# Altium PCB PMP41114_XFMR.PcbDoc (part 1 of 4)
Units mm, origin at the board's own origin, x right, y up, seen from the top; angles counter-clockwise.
Board outline 70 x 173.04 mm, 10 copper layers (Top Layer, Layer 2, Layer 3, Layer 4, Layer 5, Layer 6, Layer 7, Layer 8, Layer 9, Bottom Layer 1), stack 2.98 mm thick; 147 components, 149 nets, 547 pads, 972 vias.
Unrouted connection lines stored in the file: 2.
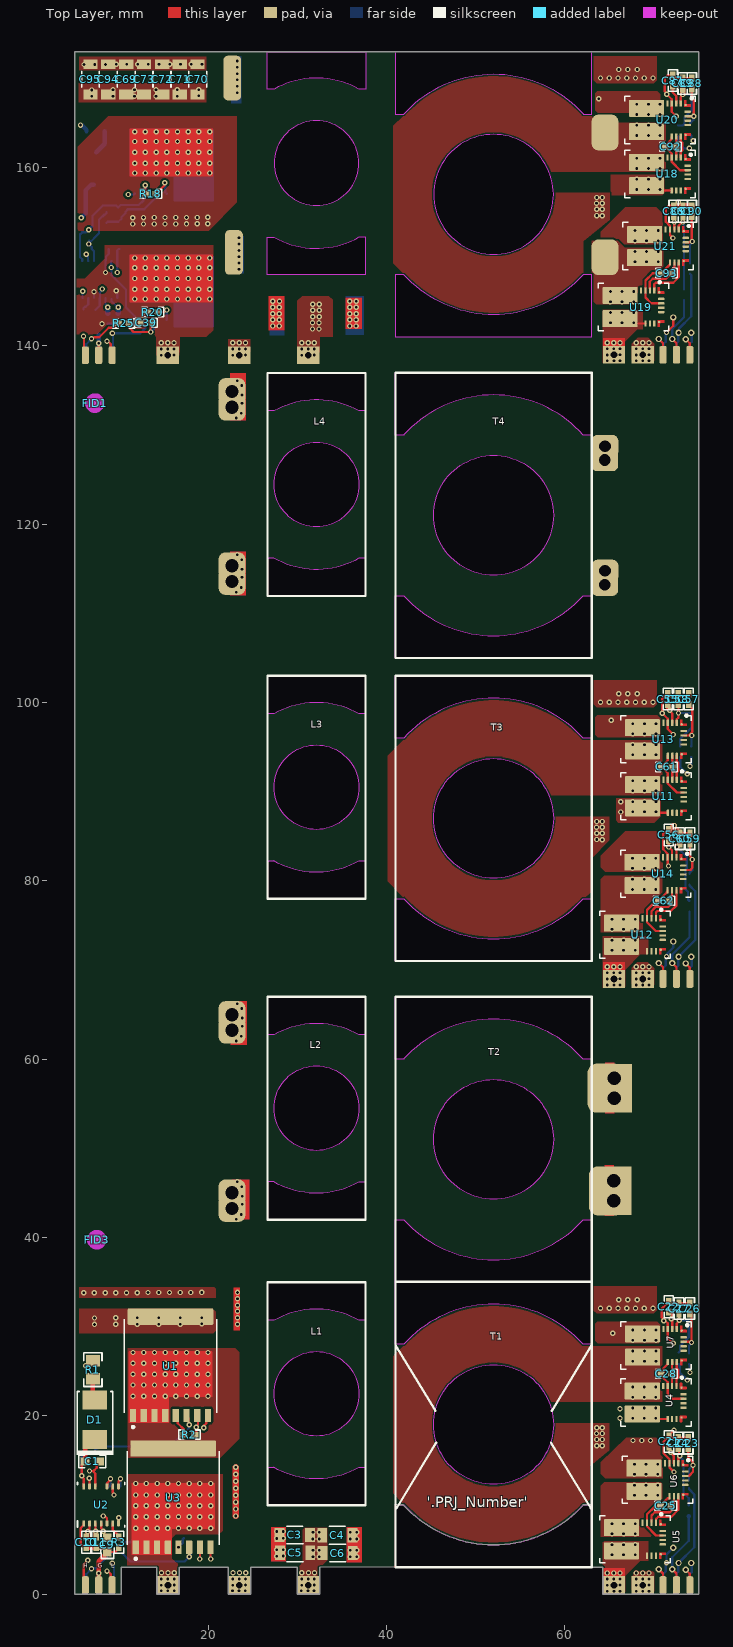
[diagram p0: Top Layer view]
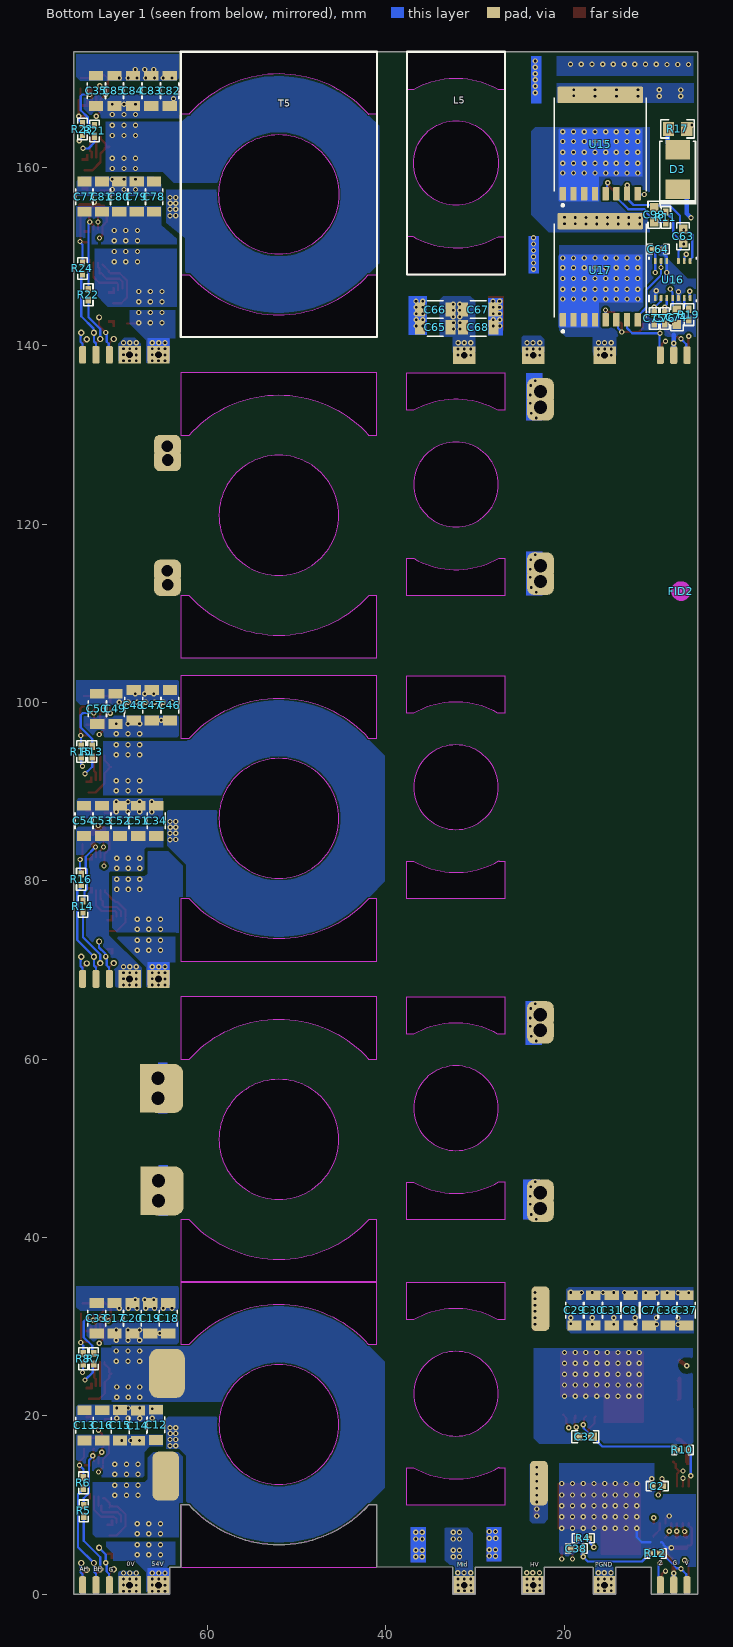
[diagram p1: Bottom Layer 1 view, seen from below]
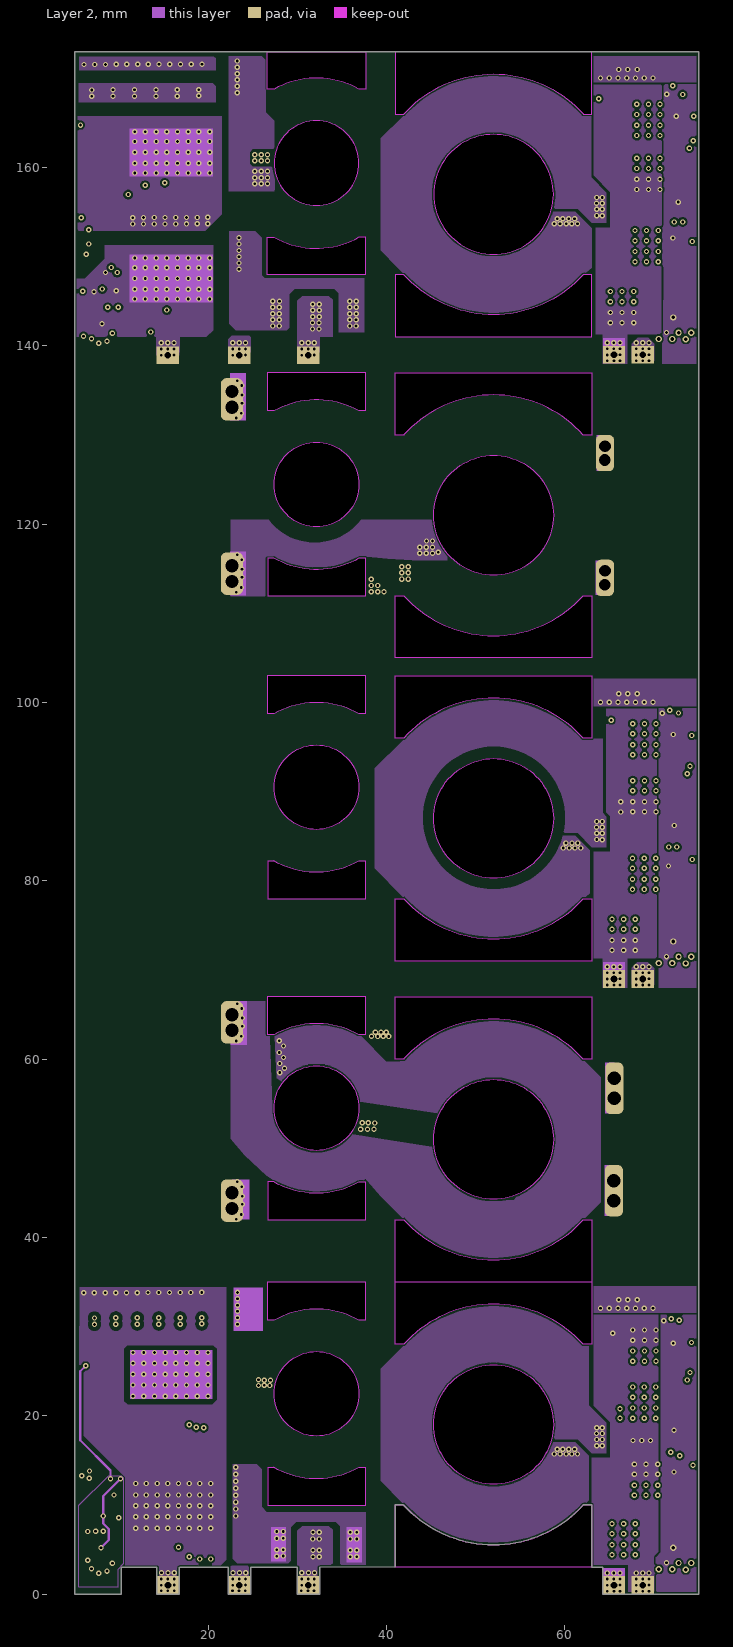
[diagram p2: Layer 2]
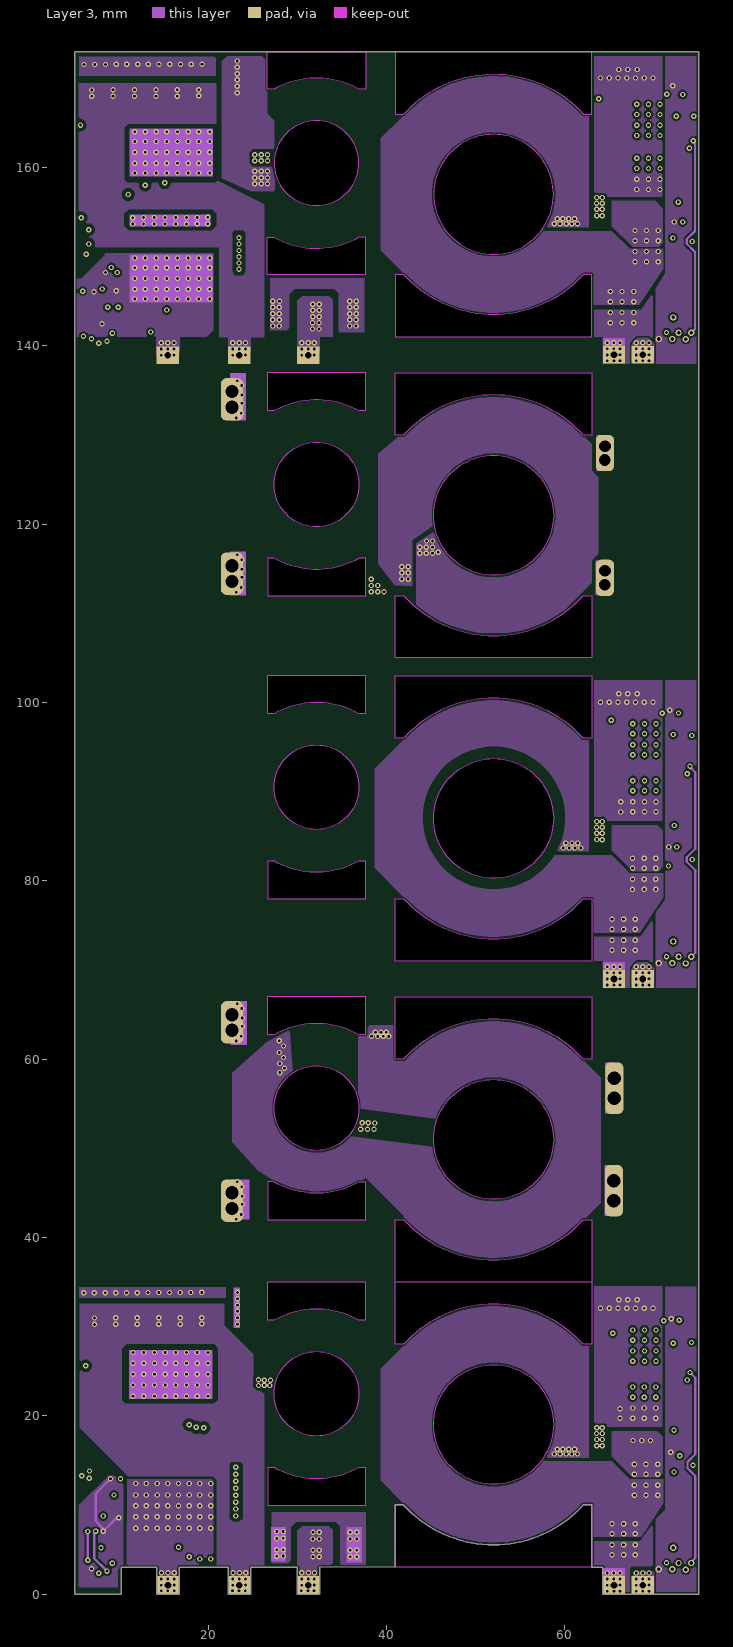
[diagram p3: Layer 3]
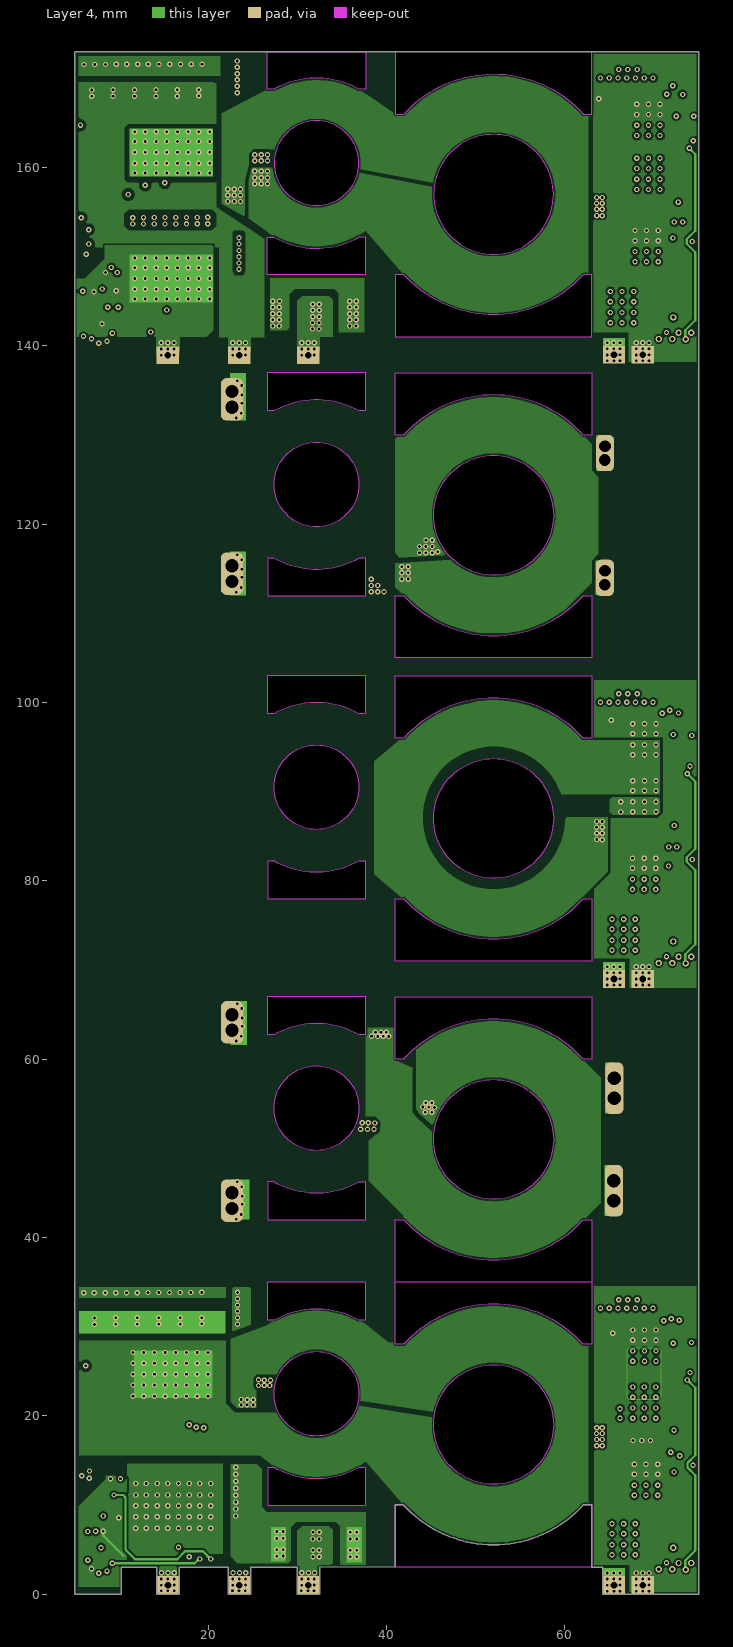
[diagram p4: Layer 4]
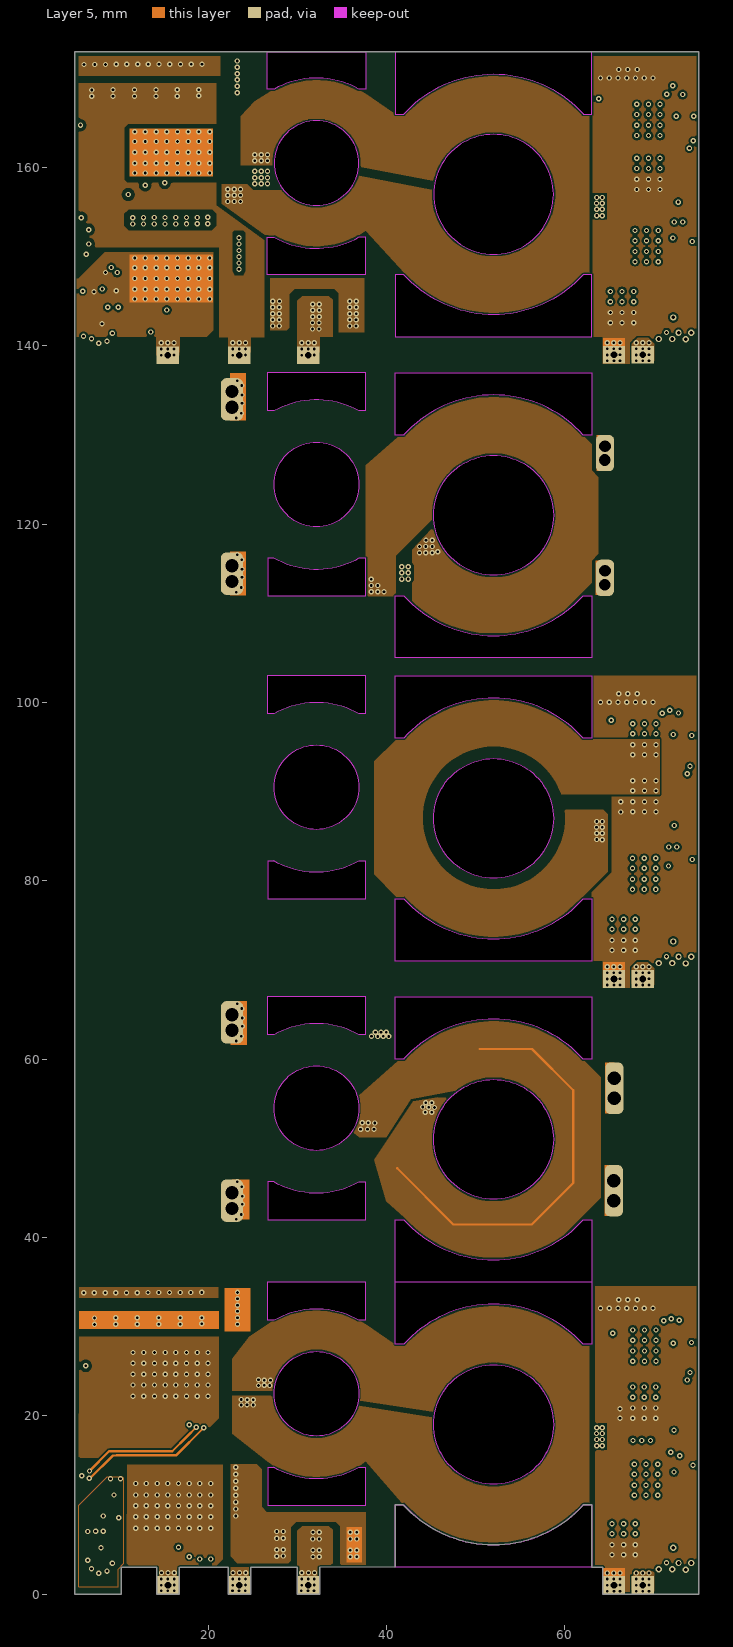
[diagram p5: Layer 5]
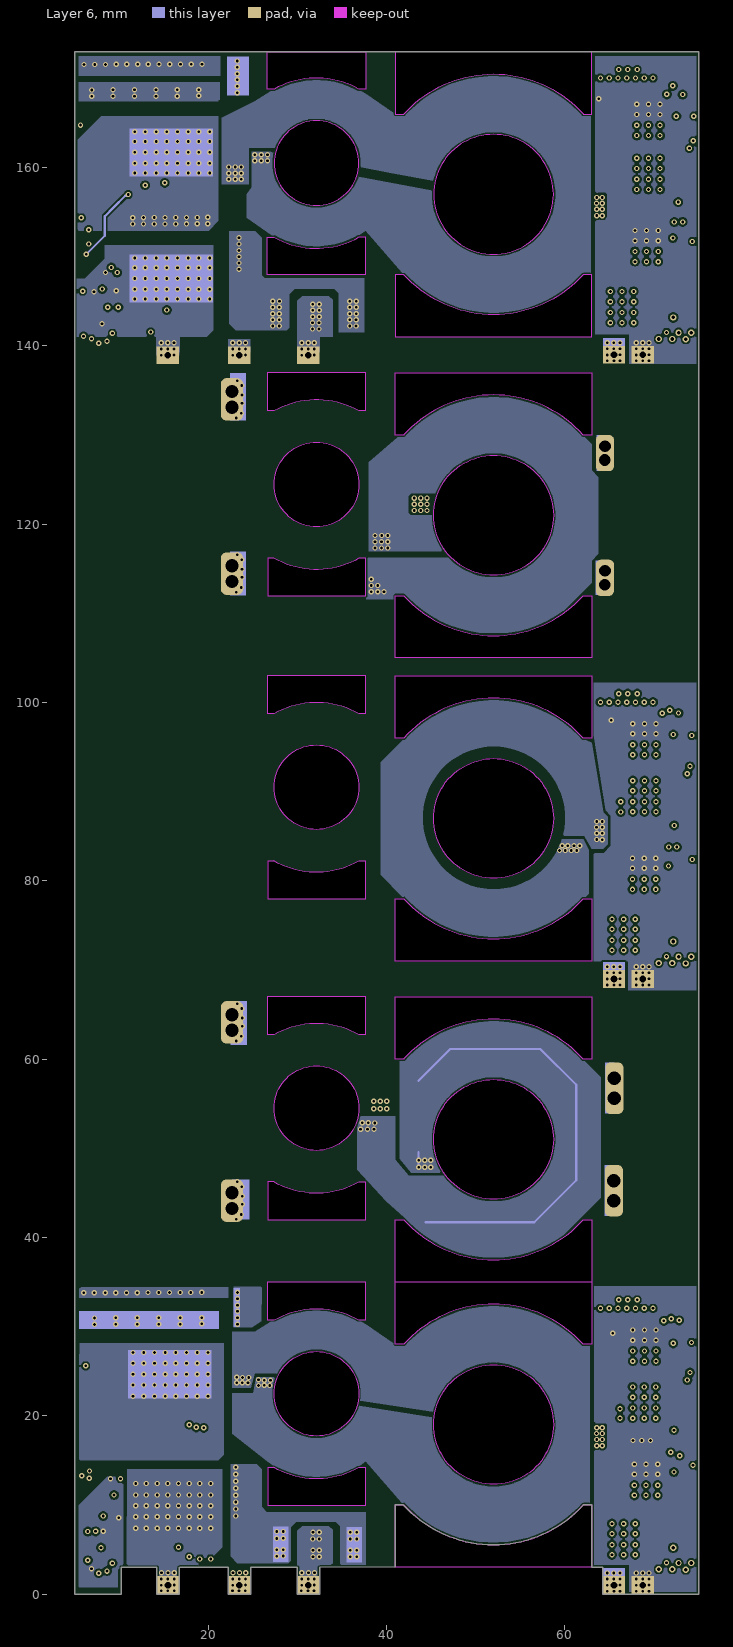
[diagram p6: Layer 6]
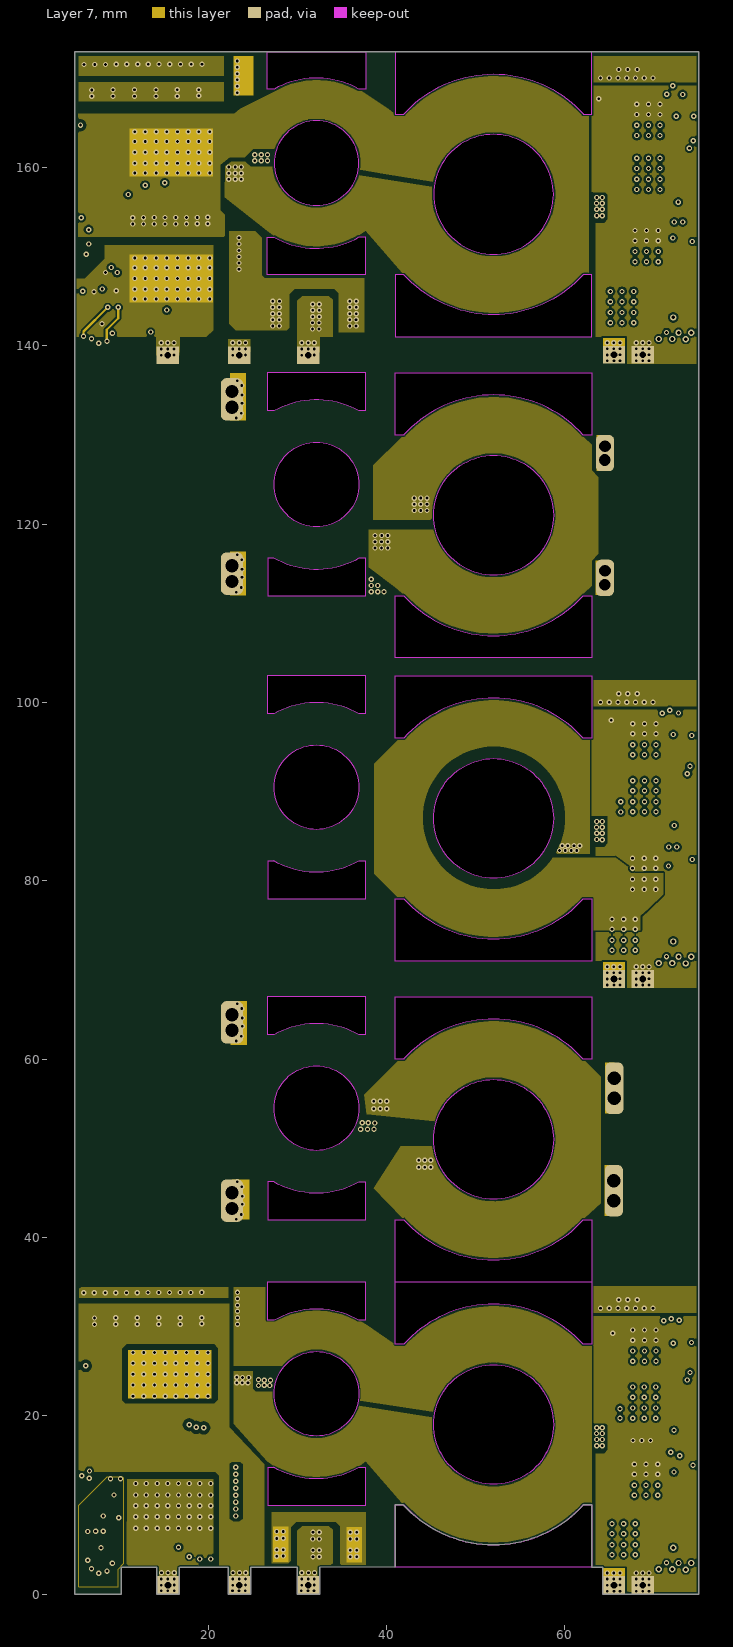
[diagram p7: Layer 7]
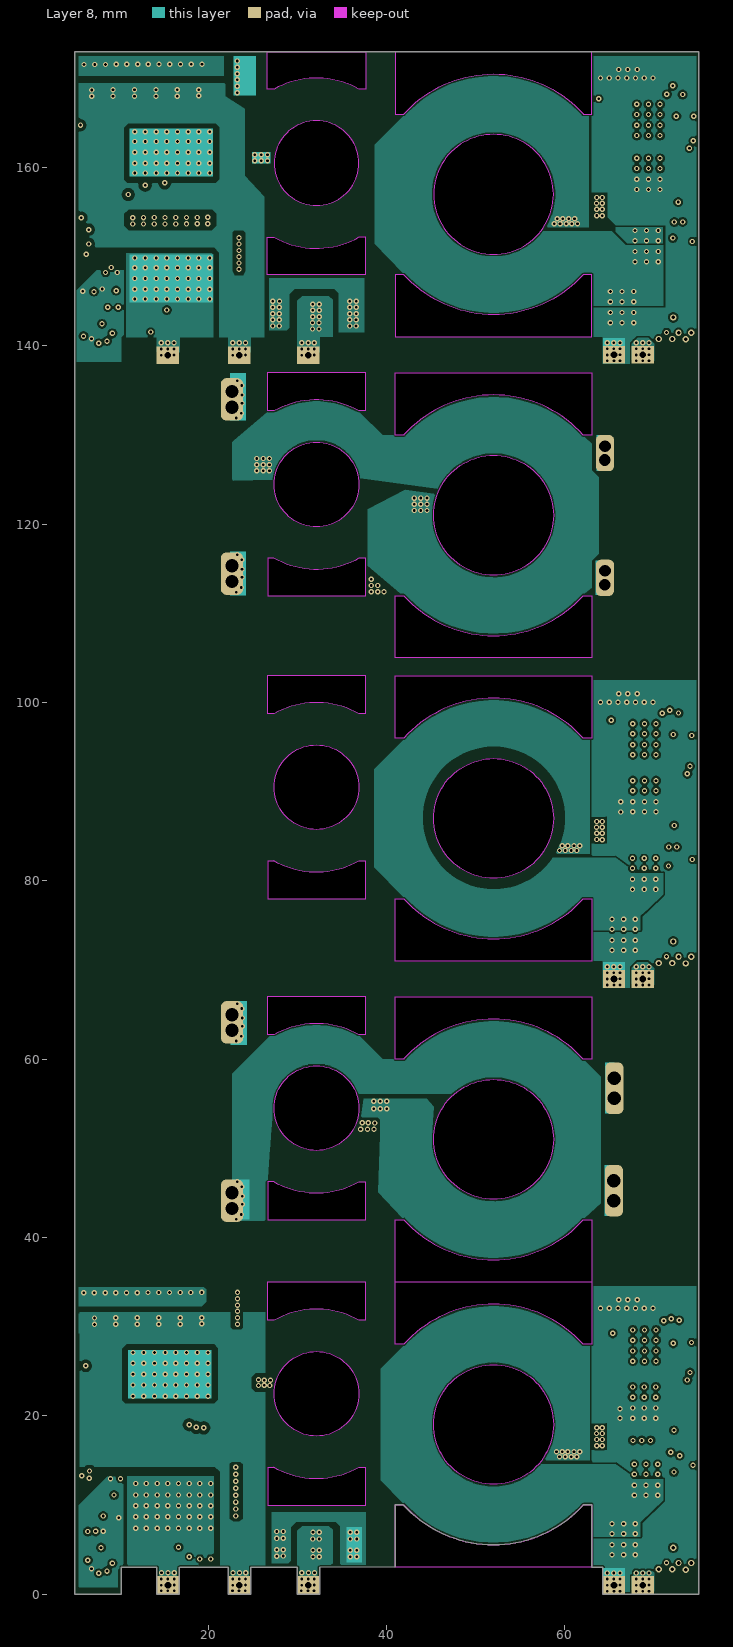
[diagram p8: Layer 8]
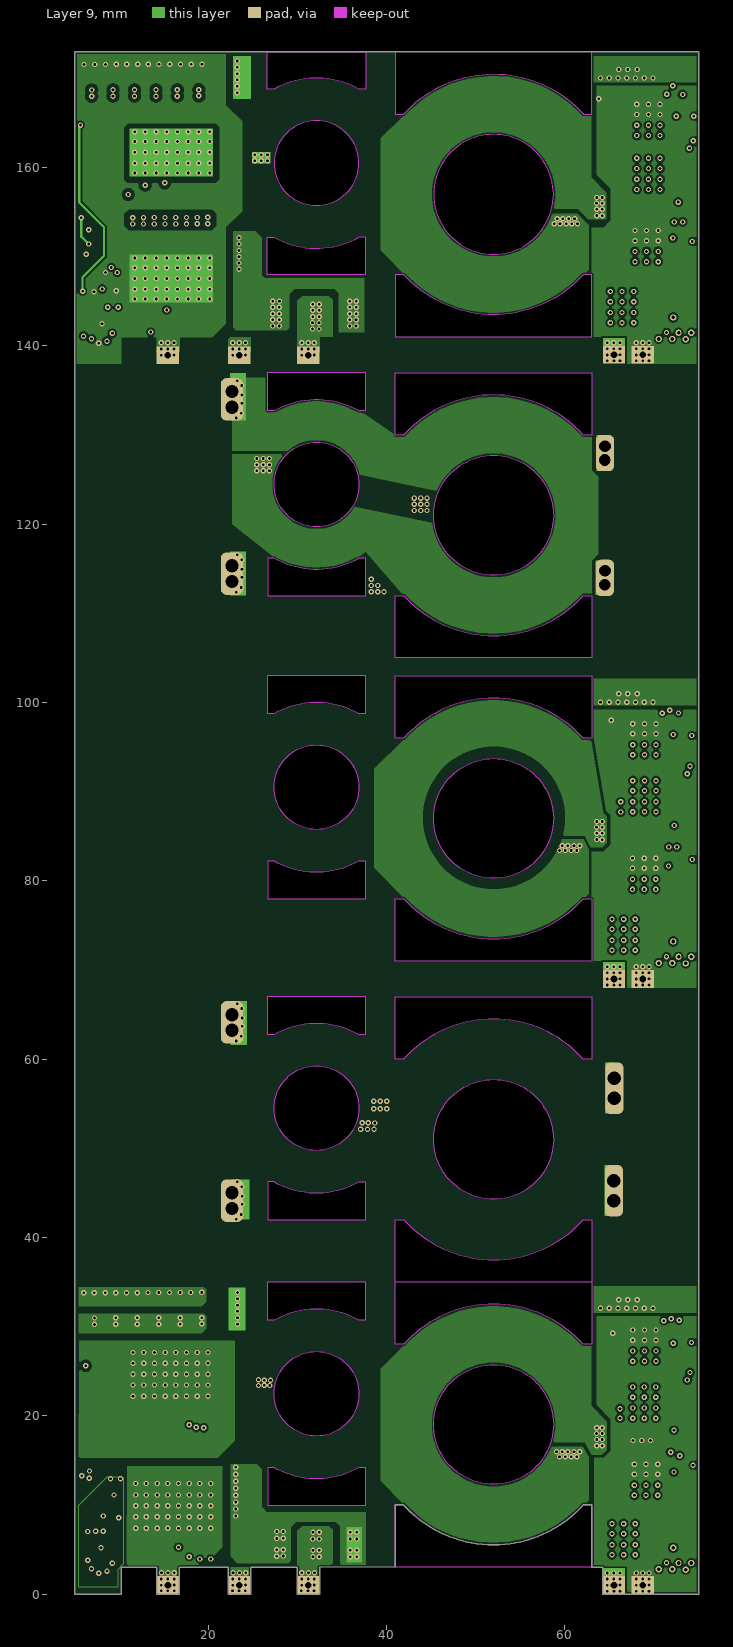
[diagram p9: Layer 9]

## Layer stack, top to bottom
Top Solder: solder mask 0.0102, Solder Resist, Dk 3.5
Top Layer: signal copper 0.07
Dielectric 7: prepreg 0.2, PP-006, Dk 4.1
Layer 2: signal copper 0.105
Dielectric 1: core 0.25, PP-006, Dk 4.1
Layer 3: signal copper 0.105
Dielectric 2: prepreg 0.2, PP-006, Dk 4.1
Layer 4: signal copper 0.105
Dielectric 3: core 0.25, PP-006, Dk 4.1
Layer 5: signal copper 0.105
Dielectric1: prepreg 0.2, FR-4 High Tg, Dk 4.8
Layer 6: signal copper 0.105
Dielectric 4: core 0.25, PP-006, Dk 4.1
Layer 7: signal copper 0.105
Dielectric 5: prepreg 0.2, PP-006, Dk 4.1
Layer 8: signal copper 0.105
Dielectric 6: core 0.25, PP-006, Dk 4.1
Layer 9: signal copper 0.105
Dielectric 8: prepreg 0.2, PP-006, Dk 4.1
Bottom Layer 1: signal copper 0.07
Bottom Solder: solder mask 0.0102, Solder Resist, Dk 3.5

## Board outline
5,0 10.25,0 10.25,3 14.231,3 14.231,-0.038 16.75,-0.038 16.75,2.962 16.78,3 22.243,3 22.243,0 24.784,0 24.784,3 29.993,3 29.993,0 32.5,0 32.5,3 41,3.064 41,10.012 41.883,10 ccw(c51.986,19.186) 62.088,10 63,10 63,3.018 64.25,3.018 64.25,0 75,0 75,173 5,173

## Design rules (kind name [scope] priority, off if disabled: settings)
AcuteAngle [All] p1: minimum=4.50000000000000E+0001 checktracksonly=TRUE
AssemblyTestPointUsage [All] p1: valid=2
BoardOutlineClearance BoardOutlineClearance_MountingHoles [OnCopper and InComponentClass('Mounting Holes')] p1: gap=0.5 ignorepadtopadclearanceinfootprint=FALSE
BoardOutlineClearance BoardOutlineClearance_Poly [OnCopper and IsPoly] p2: gap=0.254 ignorepadtopadclearanceinfootprint=FALSE
BoardOutlineClearance [OnCopper and Not InComponentClass('Logo') and not InComponentClass('FiducialMark') and not InRegion(1000,500,4000,800) and not InPoly] p3: gap=0.254 ignorepadtopadclearanceinfootprint=FALSE
Clearance Clearance_Surface [(IsPolygon AND InLayerClass('Component Layers'))] p1: gap=0.178 ignorepadtopadclearanceinfootprint=FALSE
Clearance Clearance_Keepouts [((IsTrack Or IsArc) And Not InPoly) And IsFree and IsKeepOut vs ((IsTrack Or IsArc) And Not InPoly) And IsFree and IsKeepOut] p2: gap=0 ignorepadtopadclearanceinfootprint=FALSE
Clearance Clearance_Poly [InPolygon] p3: gap=0.229 ignorepadtopadclearanceinfootprint=TRUE
Clearance Clearance_FiducialMark [IsKeepOut and InComponentClass('FiducialMark') vs IsPad and InComponentClass('FiducialMark')] p4: gap=0 ignorepadtopadclearanceinfootprint=FALSE
Clearance Clearance_1 [(ExistsOnLayer('Layer 2') Or ExistsOnLayer('Layer 3') Or ExistsOnLayer('Layer 4') Or ExistsOnLayer('Layer 5') Or ExistsOnLayer('Layer 6') Or ExistsOnLayer('Layer 7') Or ExistsOnLayer('Layer 8') Or ExistsOnLayer('Layer 9')) vs (ExistsOnLayer('Layer 2') Or ExistsOnLayer('Layer 3') Or ExistsOnLayer('Layer 4') Or ExistsOnLayer('Layer 5') Or ExistsOnLayer('Layer 6') Or ExistsOnLayer('Layer 7') Or ExistsOnLayer('Layer 8') Or ExistsOnLayer('Layer 9'))] p5: gap=0.2 ignorepadtopadclearanceinfootprint=TRUE sourcerule=57 cellrowname=All cellrowtype=0 cellcolname=All cellcoltype=0 innerlayers=TRUE
Clearance Clearance_2 [(ExistsOnLayer('Top Layer') Or ExistsOnLayer('Bottom Layer 1')) vs (ExistsOnLayer('Top Layer') Or ExistsOnLayer('Bottom Layer 1'))] p6: gap=0.2 ignorepadtopadclearanceinfootprint=TRUE sourcerule=57 cellrowname=All cellrowtype=0 cellcolname=All cellcoltype=0 outerlayers=TRUE
Clearance [All] p7: gap=0.2 ignorepadtopadclearanceinfootprint=TRUE ismatrix=TRUE
ComponentClearance ComponentClearance_MountingHoles_FiducialMarks [InComponentClass('Mounting Holes') vs InComponentClass('FiducialMark')] p1: gap=1.27 collisioncheckmode=3 verticalgap=0.254 showdistances=FALSE
ComponentClearance ComponentClearance_Shunt [InComponentClass('Header') vs InComponentClass('Shunt')] p2: gap=0 collisioncheckmode=3 verticalgap=0 showdistances=FALSE
ComponentClearance ComponentClearance_Logo [InComponentClass('Logo')] p3: gap=0.762 collisioncheckmode=3 verticalgap=0.254 showdistances=FALSE
ComponentClearance ComponentClearance_ScrewToNut [(HasFootprint('NY PMS 440 0025 PH')) vs (HasFootprint('Keystone_1902C'))] p4: gap=0.127 collisioncheckmode=3 verticalgap=0.254 showdistances=FALSE
ComponentClearance ComponentClearance_MountingHoles [InComponentClass('Mounting Holes')] p5: gap=2.54 collisioncheckmode=3 verticalgap=2540 showdistances=FALSE
ComponentClearance ComponentClearance_SmallPassives [HasFootprint('0201*') or HasFootprint('0402*') or HasFootprint('0508') or HasFootprint('0603*') or HasFootprint('0612') or HasFootprint('0805*') or HasFootprint('0815*') or HasFootprint('0830*') or HasFootprint('1206*') or HasFootprint('1210*') or HasFootprint('1808*') or HasFootprint('1812*') or HasFootprint('1825*') or HasFootprint('2010*') or HasFootprint('2220*') or HasFootprint('2225*') or HasFootprint('2512*') or HasFootprint('2728*') or HasFootprint('3518*') vs HasFootprint('0201*') or HasFootprint('0402*') or HasFootprint('0508') or HasFootprint('0603*') or HasFootprint('0612') or HasFootprint('0805*') or HasFootprint('0815*') or HasFootprint('0830*') or HasFootprint('1206*') or HasFootprint('1210*') or HasFootprint('1808*') or HasFootprint('1812*') or HasFootprint('1825*') or HasFootprint('2010*') or HasFootprint('2220*') or HasFootprint('2225*') or HasFootprint('2512*') or HasFootprint('2728*') or HasFootprint('3518*')] p6 off: gap=0.38 collisioncheckmode=3 verticalgap=0.254 showdistances=FALSE
ComponentClearance ComponentClearance_THtoSMT [IsThruComponent vs IsSMTComponent] p7: gap=0.762 collisioncheckmode=3 verticalgap=0.762 showdistances=FALSE
ComponentClearance ComponentClearance_THtoTH [IsThruComponent vs IsThruComponent] p8: gap=0.508 collisioncheckmode=3 verticalgap=0.762 showdistances=FALSE
ComponentClearance [All] p9: gap=0 collisioncheckmode=3 verticalgap=0.254 showdistances=FALSE
FabricationTestPointUsage TestPointUsage [All] p1: valid=2 allowmultiple=FALSE
FabricationTestpoint Testpoint [All] p1: side=3 testpointundercomponent=TRUE minsize=1.016 maxsize=2.54 preferedsize=1.524 minholesize=0 maxholesize=1.016 preferedholesize=0.813 testpointgrid=0.025 allowsidetop=TRUE allowsidebottom=TRUE usegrid=TRUE gridtolerance=0
FanoutControl Fanout_LCC [IsLCC] p1: bgadir=Out bgaviamode=Centered fanoutstyle=Auto fanoutdirection=Alternating viagrid=0.025 // Fanout_LCC (Default Rule)
FanoutControl Fanout_BGA [IsBGA] p2: bgadir=Out bgaviamode=Centered fanoutstyle=Auto fanoutdirection=Alternating viagrid=0.025 // Fanout_BGA (Default Rule)
FanoutControl Fanout_Default [All] p4: bgadir=Out bgaviamode=Centered fanoutstyle=Auto fanoutdirection=Alternating viagrid=0.025 // Fanout_Default (Default Rule)
FanoutControl Fanout_Small [(CompPinCount < 5)] p5: bgadir=Out bgaviamode=Centered fanoutstyle=Auto fanoutdirection=OutThenIn viagrid=0.025 // Fanout_Small (Default Rule)
HoleSize [All] p1: absolutevalues=TRUE maxlimit=6.375 minlimit=0.2 maxpercent=80.000 minpercent=20.000
MinimumAnnularRing MinimumAnnularRing_ThermalPadVias [IsVia and InAnyComponent] p1: minimumring=0.15
MinimumAnnularRing [All] p2: minimumring=0.15
MinimumSolderMaskSliver MinimumSolderMaskSliver_Logo [InComponentClass('Logo') vs InComponentClass('Logo')] p1: minsoldermaskwidth=0.018
MinimumSolderMaskSliver [All] p2: minsoldermaskwidth=0.1
PlaneConnect [All] p1: planeconnectstyle=Relief reliefexpansion=0.254 reliefentries=4 reliefconductorwidth=0.254 reliefairgap=0.254
PolygonConnect [All] p1: connectstyle=Direct reliefconductorwidth=0.254 reliefentries=4 polygonreliefangle="90 Angle" airgapwidth=0.254
RoutingVias [All] p1: holewidth=0.711 width=1.27 viastyle="Through Hole" minholewidth=0.3 minwidth=0.6 maxholewidth=0.711 maxwidth=1.27
SilkToBoardRegionClearance [Not ((IsComment or IsDesignator) And (Hide <> 'False')) and not InRegion(1000,500,4000,800)] p1:
SilkToSilkClearance SilkToSilkClearance_Pb-FreeLogo [(HasFootprint('Pb-Free_Overlay_Medium') OR HasFootprint('Pb-Free_Overlay_Small')) vs (HasFootprint('Pb-Free_Overlay_Medium') OR HasFootprint('Pb-Free_Overlay_Small'))] p1: silktosilkclearance=0
SilkToSilkClearance [All] p2: silktosilkclearance=0.1
SilkToSolderMaskClearance SilkToComponentPadClearance [(IsPad or IsFill or IsRegion) and InAnycomponent] p1: minsilkscreentomaskgap=0.127 clearancetoexposedcopper=TRUE
SilkToSolderMaskClearance "Silk to Solder Mask Opening" [All] p2: minsilkscreentomaskgap=0.1 clearancetoexposedcopper=FALSE
SolderMaskExpansion [All] p1: expansion=0.05 istentingtop=FALSE
UnRoutedNet [All] p1: checkbadconnections=TRUE
Width [All] p1: maxlimit=2 minlimit=0.254 preferedwidth=0.254
15 further rules are at their usual default settings.

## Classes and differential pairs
component class PMP41114_D2D_Sheet5: C35 C39 C63 C64 C65 C66 C67 C68 C69 C70 C71 C72 C73 C74 C75 C76 C77 C78 C79 C80 C81 C82 C83 C84 C85 C86 C87 C88 C89 C90 C91 C92 C93 C94 C95 C98 D3 R11 R17 R18 R19 R20 R21 R22 R23 R24 R25 U15 U16 U17 U18 U19 U20 U21
component class PMP41114_D2D_Sheet3: C34 C46 C47 C48 C49 C50 C51 C52 C53 C54 C55 C56 C57 C58 C59 C60 C61 C62 R13 R14 R15 R16 U11 U12 U13 U14
component class PMP41114_D2D_Sheet1: C1 C2 C3 C4 C5 C6 C7 C8 C9 C10 C11 C12 C13 C14 C15 C16 C17 C18 C19 C20 C21 C22 C23 C24 C25 C26 C27 C28 C29 C30 C31 C32 C33 C36 C37 C38 D1 L1 R1 R2 R3 R4 R5 R6 R7 R8 R10 R12 T1 U1 U2 U3 U4 U5 U6 U7
component class PMP41114_D2D_Hardware: !PCB FID1 FID2 FID3 L2 L3 L4 L5 T2 T3 T4 T5
component class FiducialMark: FID1 FID2 FID3

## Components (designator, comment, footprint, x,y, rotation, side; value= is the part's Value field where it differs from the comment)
C1 "CGJ3E1X7R1E105K080AC" 0603 6.987,14.87 r0 top value=1uF
C2 "C1005X7R1H104K050BB" 0402 9.561,12.102 r0 bottom value=0.1uF
C3 "C1206C223KDRACTU" 1206_190 29.702,6.627 r0 top value=0.022uF
C4 "C1206C223KDRACTU" 1206_190 34.489,6.598 r180 top value=0.022uF
C5 "C1206C223KDRACTU" 1206_190 29.732,4.622 r0 top value=0.022uF
C6 "C1206C223KDRACTU" 1206_190 34.517,4.599 r180 top value=0.022uF
C7 "C1206C223KDRACTU" 1206_190 10.485,31.82 r90 bottom value=0.022uF
C8 "C1206C223KDRACTU" 1206_190 12.572,31.82 r90 bottom value=0.022uF
C9 "CGJ3E1X7R1E105K080AC" 0603 8.695,5.515 r270 top value=1uF
C10 "885012205055" 0402 6.323,5.805 r270 top value=100pF
C11 "885012205055" 0402 7.421,5.805 r270 top value=100pF
C12 "GRM31CZ72A475KE11L" 1206_180 65.782,18.977 r270 bottom value=4.7uF
C13 "GRM31CZ72A475KE11L" 1206_180 73.798,18.919 r270 bottom value=4.7uF
C14 "GRM31CZ72A475KE11L" 1206_180 67.803,18.905 r270 bottom value=4.7uF
C15 "GRM31CZ72A475KE11L" 1206_180 69.81,18.933 r270 bottom value=4.7uF
C16 "GRM31CZ72A475KE11L" 1206_180 71.802,18.923 r270 bottom value=4.7uF
C17 "GRM31CZ72A475KE11L" 1206_180 70.432,30.942 r270 bottom value=4.7uF
C18 "GRM31CZ72A475KE11L" 1206_180 64.417,30.942 r270 bottom value=4.7uF
C19 "GRM31CZ72A475KE11L" 1206_180 66.438,30.942 r270 bottom value=4.7uF
C20 "GRM31CZ72A475KE11L" 1206_180 68.428,30.942 r270 bottom value=4.7uF
C21 "GRM155R71H104ME14D" 0402 71.684,17.122 r90 top value=0.1uF
C22 "GRM155R71H104ME14D" 0402 71.656,32.224 r90 top value=0.1uF
C23 "CC0402KRX7R9BB101" 0402 73.85,16.934 r90 top value=100pF
C24 "CC0402KRX7R9BB101" 0402 72.725,16.934 r90 top value=100pF
C25 "C1005X7R1H104K050BE" 0402 71.331,9.913 r180 top value=0.1uF
C26 "CC0402KRX7R9BB101" 0402 74.023,32.031 r90 top value=100pF
C27 "CC0402KRX7R9BB101" 0402 72.804,32.031 r90 top value=100pF
C28 "C1005X7R1H104K050BE" 0402 71.389,24.718 r180 top value=0.1uF
C29 "C1206C223KDRACTU" 1206_190 18.834,31.82 r90 bottom value=0.022uF
C30 "C1206C223KDRACTU" 1206_190 16.747,31.82 r90 bottom value=0.022uF
C31 "C1206C223KDRACTU" 1206_190 14.659,31.82 r90 bottom value=0.022uF
C32 "CGJ3E1X7R1E105K080AC" 0603 17.623,17.644 r0 bottom value=1uF
C33 "GRM31CZ72A475KE11L" 1206_180 72.436,30.942 r270 bottom value=4.7uF
C34 "GRM31CZ72A475KE11L" 1206_180 65.761,86.717 r270 bottom value=4.7uF
C35 "GRM31CZ72A475KE11L" 1206_180 72.501,168.6 r270 bottom value=4.7uF
C36 "C1206C223KDRACTU" 1206_190 8.397,31.82 r90 bottom value=0.022uF
C37 "C1206C223KDRACTU" 1206_190 6.31,31.82 r90 bottom value=0.022uF
C38 "C1005X7R1H104K050BB" 0402 18.626,5.101 r180 bottom value=0.1uF
C39 "C1005X7R1H104K050BB" 0402 13.044,142.592 r180 top value=0.1uF
C46 "GRM31CZ72A475KE11L" 1206_180 64.213,99.694 r270 bottom value=4.7uF
C47 "GRM31CZ72A475KE11L" 1206_180 66.251,99.694 r270 bottom value=4.7uF
C48 "GRM31CZ72A475KE11L" 1206_180 68.289,99.694 r270 bottom value=4.7uF
C49 "GRM31CZ72A475KE11L" 1206_180 70.326,99.294 r270 bottom value=4.7uF
C50 "GRM31CZ72A475KE11L" 1206_180 72.364,99.294 r270 bottom value=4.7uF
C51 "GRM31CZ72A475KE11L" 1206_180 67.788,86.717 r270 bottom value=4.7uF
C52 "GRM31CZ72A475KE11L" 1206_180 69.815,86.717 r270 bottom value=4.7uF
C53 "GRM31CZ72A475KE11L" 1206_180 71.842,86.717 r270 bottom value=4.7uF
C54 "GRM31CZ72A475KE11L" 1206_180 73.869,86.717 r270 bottom value=4.7uF
C55 "GRM155R71H104ME14D" 0402 71.547,100.391 r90 top value=0.1uF
C56 "GRM155R71H104ME14D" 0402 71.653,85.15 r90 top value=0.1uF
C57 "CC0402KRX7R9BB101" 0402 73.89,100.391 r90 top value=100pF
C58 "CC0402KRX7R9BB101" 0402 72.734,100.391 r90 top value=100pF
C59 "CC0402KRX7R9BB101" 0402 74.032,84.732 r90 top value=100pF
C60 "CC0402KRX7R9BB101" 0402 72.887,84.732 r90 top value=100pF
C61 "C1005X7R1H104K050BE" 0402 71.407,92.775 r180 top value=0.1uF
C62 "C1005X7R1H104K050BE" 0402 71.11,77.773 r180 top value=0.1uF
C63 "CGJ3E1X7R1E105K080AC" 0603 6.664,152.314 r90 bottom value=1uF
C64 "C1005X7R1H104K050BB" 0402 9.44,150.865 r180 bottom value=0.1uF
C65 "C1206C223KDRACTU" 1206_190 34.457,142.101 r180 bottom value=0.022uF
C66 "C1206C223KDRACTU" 1206_190 34.457,144.076 r180 bottom value=0.022uF
C67 "C1206C223KDRACTU" 1206_190 29.644,144.083 r0 bottom value=0.022uF
C68 "C1206C223KDRACTU" 1206_190 29.644,142.101 r0 bottom value=0.022uF
C69 "C1206C223KDRACTU" 1206_190 10.795,169.901 r90 top value=0.022uF
C70 "C1206C223KDRACTU" 1206_190 18.805,169.901 r90 top value=0.022uF
C71 "C1206C223KDRACTU" 1206_190 16.815,169.899 r90 top value=0.022uF
C72 "C1206C223KDRACTU" 1206_190 14.827,169.899 r90 top value=0.022uF
C73 "C1206C223KDRACTU" 1206_190 12.8,169.901 r90 top value=0.022uF
C74 "CGJ3E1X7R1E105K080AC" 0603 7.357,143.222 r270 bottom value=1uF
C75 "885012205055" 0402 9.91,143.076 r270 bottom value=100pF
C76 "885012205055" 0402 8.733,143.076 r270 bottom value=100pF
C77 "GRM31CZ72A475KE11L" 1206_180 73.799,156.748 r270 bottom value=4.7uF
C78 "GRM31CZ72A475KE11L" 1206_180 66.002,156.748 r270 bottom value=4.7uF
C79 "GRM31CZ72A475KE11L" 1206_180 67.951,156.748 r270 bottom value=4.7uF
C80 "GRM31CZ72A475KE11L" 1206_180 69.9,156.748 r270 bottom value=4.7uF
C81 "GRM31CZ72A475KE11L" 1206_180 71.849,156.748 r270 bottom value=4.7uF
C82 "GRM31CZ72A475KE11L" 1206_180 64.251,168.6 r270 bottom value=4.7uF
C83 "GRM31CZ72A475KE11L" 1206_180 66.313,168.6 r270 bottom value=4.7uF
C84 "GRM31CZ72A475KE11L" 1206_180 68.376,168.6 r270 bottom value=4.7uF
C85 "GRM31CZ72A475KE11L" 1206_180 70.438,168.6 r270 bottom value=4.7uF
C86 "GRM155R71H104ME14D" 0402 72.204,155.112 r90 top value=0.1uF
C87 "GRM155R71H104ME14D" 0402 72.111,169.769 r90 top value=0.1uF
C88 "CC0402KRX7R9BB101" 0402 74.242,169.442 r90 top value=100pF
C89 "CC0402KRX7R9BB101" 0402 73.209,169.442 r90 top value=100pF
C90 "CC0402KRX7R9BB101" 0402 74.242,155.112 r90 top value=100pF
C91 "CC0402KRX7R9BB101" 0402 73.241,155.112 r90 top value=100pF
C92 "C1005X7R1H104K050BE" 0402 71.849,162.343 r180 top value=0.1uF
C93 "C1005X7R1H104K050BE" 0402 71.4,148.158 r180 top value=0.1uF
C94 "C1206C223KDRACTU" 1206_190 8.79,169.901 r90 top value=0.022uF
C95 "C1206C223KDRACTU" 1206_190 6.785,169.901 r90 top value=0.022uF
C98 "CGJ3E1X7R1E105K080AC" 0603 9.91,154.713 r90 bottom value=1uF
D1 "GB01SLT06-214" SMB 7.284,19.549 r90 top value=650V
D3 "GB01SLT06-214" SMB 7.265,159.789 r90 bottom value=650V
FID1 "Fiducial" Fiducial10-20 7.287,133.583 r0 top
FID2 "Fiducial" Fiducial10-20 6.903,112.5 r180 bottom
FID3 "Fiducial" Fiducial10-20 7.5,39.75 r0 top
L1 "Core" ER25/10/11 32.139,22.471 r0 top locked
L2 "Core" ER25/10/11 32.139,54.5 r0 top locked
L3 "Core" ER25/10/11 32.139,90.5 r0 top locked
L4 "Core" ER25/10/11 32.139,124.462 r0 top locked
L5 "Core" ER25/10/11 32.139,160.5 r180 bottom
R1 "RC0805JR-072R2L" 0805_HV 7.063,25.165 r270 top value=2.2
R2 "CRCW040230K1FKED" 0402 17.891,17.882 r180 top value=30.1k
R3 "CRCW040210K0JNED" 0402 9.98,5.818 r90 top value=10k
R4 "CRCW040230K1FKED" 0402 17.854,6.262 r180 bottom value=30.1k
R5 "RC0402JR-0751RL" 0402 73.893,9.333 r270 bottom value=51
R6 "RC0402JR-0751RL" 0402 73.924,12.473 r270 bottom value=51
R7 "RC0402JR-0751RL" 0402 72.769,26.39 r270 bottom value=51
R8 "RC0402JR-0751RL" 0402 73.931,26.39 r270 bottom value=51
R10 "RC0402JR-070RL" 0402 6.729,16.172 r0 bottom value=0
R11 "RC0402JR-070RL" 0402 8.592,154.418 r270 bottom value=0
R12 "RC0402JR-070RL" 0402 9.763,4.568 r0 bottom value=0
R13 "RC0402JR-0751RL" 0402 72.944,94.5 r270 bottom value=51
R14 "RC0402JR-0751RL" 0402 73.978,77.126 r270 bottom value=51
R15 "RC0402JR-0751RL" 0402 74.174,94.5 r270 bottom value=51
R16 "RC0402JR-0751RL" 0402 74.178,80.173 r270 bottom value=51
R17 "RC0805JR-072R2L" 0805_HV 7.275,164.34 r0 bottom value=2.2
R18 "CRCW040230K1FKED" 0402 13.542,157.073 r0 top value=30.1k
R19 "CRCW040210K0JNED" 0402 6.01,143.51 r90 bottom value=10k
R20 "CRCW040230K1FKED" 0402 13.766,143.797 r0 top value=30.1k
R21 "RC0402JR-0751RL" 0402 72.681,164.112 r270 bottom value=51
R22 "RC0402JR-0751RL" 0402 73.366,145.734 r270 bottom value=51
R23 "RC0402JR-0751RL" 0402 74.034,164.321 r270 bottom value=51
R24 "RC0402JR-0751RL" 0402 74.034,148.686 r270 bottom value=51
R25 "RC0402JR-070RL" 0402 10.51,142.526 r0 top value=0
T1 "Core" PQ32 52,19.018 r0 top locked
T2 "Core" PQ32 52,51 r0 top locked
T3 "Core" PQ32 52,87 r0 top locked
T4 "Core" PQ32 52,121 r0 top
T5 "Core" PQ32 52,157 r180 bottom
U1 "LMG365x" KLA0009A-MFG 15.763,25.572 r90 top
U2 "UCC21225ANPL" NPL0013A 7.989,10.005 r90 top locked
U3 "LMG365x" KLA0009A-MFG 16.063,10.79 r90 top
U4 "LMG3100R017" VBE0015A-MFG 70.203,21.483 r270 top
U5 "LMG3100R017" VBE0015A-MFG 67.885,6.155 r270 top
U6 "LMG3100R017" VBE0015A-MFG 70.4,12.825 r270 top
U7 "LMG3100R017" VBE0015A-MFG 70.224,27.875 r270 top
U11 "LMG3100R017" VBE0015A-MFG 70.224,89.483 r270 top
U12 "LMG3100R017" VBE0015A-MFG 67.885,73.955 r270 top
U13 "LMG3100R017" VBE0015A-MFG 70.224,95.875 r270 top
U14 "LMG3100R017" VBE0015A-MFG 70.191,80.787 r270 top
U15 "LMG365x" KLA0009A-MFG 15.95,162.61 r90 bottom
U16 "UCC21225ANPL" NPL0013A 7.832,147.447 r90 bottom
U17 "LMG3656" KLA0009A-MFG 15.95,148.461 r90 bottom
U18 "LMG3100R017" VBE0015A-MFG 70.675,159.288 r270 top
U19 "LMG3100R017" VBE0015A-MFG 67.709,144.354 r270 top
U20 "LMG3100R017" VBE0015A-MFG 70.675,165.342 r270 top
U21 "LMG3100R017" VBE0015A-MFG 70.459,151.2 r270 top

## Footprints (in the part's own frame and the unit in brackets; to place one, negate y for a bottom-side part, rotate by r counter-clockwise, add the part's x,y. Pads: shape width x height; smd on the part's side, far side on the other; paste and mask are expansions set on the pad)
0402 [mm] "0402 from SM-752 data"
  rect 0.8x0.6 smd: 1(-0.6,0) 2(0.6,0)
  silkscreen extent -1.22,-0.52 1.22,0.52, body extent -0.55,-0.3 0.55,0.3, height 0.6
0603 [mm] "0603 from SM-752 data"
  rect 1x0.95 smd: 1(-0.8,0) 2(0.8,0)
  silkscreen extent -1.52,-0.69 1.52,0.69, body extent -0.87,-0.47 0.87,0.47, height 1
0805_HV [mil] "0805 with 30mil clearance between pads"
  rect 50x63 smd: 1(-40,0) 2(40,0)
  silkscreen extent -74,-40 74,40, body extent -43,-29 43,29, height 57
1206_180 [mm] "1206_180"
  rect 1.1x1.6 smd: 1(-1.7,0) 2(1.7,0)
  silkscreen extent -0.9,-1 0.9,1, body extent -1.75,-0.95 1.75,0.95, height 1.8
1206_190 [mm] "1206_190"
  rect 1.1x1.6 smd: 1(-1.7,0) 2(1.7,0)
  silkscreen extent -0.9,-1 0.9,1, body extent -1.75,-0.95 1.75,0.95, height 1.9
ER25/10/11 [mm] "Core"
  Keep-Out Layer board cut-out: 0,-4.75 -1.818,-4.388 -3.359,-3.359 -4.388,-1.818 -4.75,0 -4.75,0 -4.388,1.818 -3.359,3.359 -1.818,4.388 0,4.75 0,4.75 1.818,4.388 3.359,3.359 4.388,1.818 4.75,0 4.75,0 4.388,-1.818 3.359,-3.359 1.818,-4.388 0,-4.75
  Keep-Out Layer board cut-out: -5.493,-12.493 5.531,-12.493 5.531,-8.297 4.728,-8.297 4.728,-8.297 -0.036,-9.55 -4.79,-8.262 -4.79,-8.262 -4.8,-8.278 -5.493,-8.278
  Keep-Out Layer board cut-out: -5.5,8.3 -4.714,8.3 -4.714,8.306 0.006,9.55 4.724,8.3 4.724,8.3 4.8,8.3 5.5,8.3 5.5,12.5 -5.5,12.5
  silkscreen extent -5.5,-12.5 5.5,12.5, body extent -5.5,-12.5 5.5,12.5, height 0.25
Fiducial10-20 [mm]
  round 1 smd mask+0.5: 1(0,0)
  Top Layer keep-out circle w1.178: c0,0 r0.5
KLA0009A-MFG [mm]
  rrect14% 1.5x0.7 smd paste+0 mask-1000: 1(-5.539,4.2) 2(-5.539,3) 3(-5.539,1.8) 4(-5.539,0.6) 5(-5.539,-0.6) 6(-5.539,-1.8) 7(-5.539,-3) 8(-5.539,-4.2)
  rrect15% 1.843x9.6 smd paste-1000 mask-1000: 9(5.539,0)
  Top Layer region: -6.36,4.6 -6.351,4.635 -6.325,4.661 -6.29,4.67 -6.29,4.67 1.587,4.67 1.622,4.661 1.648,4.635 1.657,4.6 1.657,4.6 1.657,-4.6 1.648,-4.635 1.622,-4.661 1.587,-4.67 1.587,-4.67 -3.388,-4.67 -3.423,-4.661 -3.449,-4.635 -3.458,-4.6 -3.458,-4.6 -3.458,0.13 -3.462,0.149 -3.473,0.165 -3.489,0.176 -3.508,0.18 -3.508,0.18 -6.29,0.18 -6.317,0.185 -6.339,0.201 -6.355,0.223 -6.36,0.25 -6.36,0.25
  silkscreen extent -6.96,-5.18 5.24,5.18, body extent -6.46,-5.1 6.56,5.1, height 0.25
NPL0013A [mm] "SMD, 13-Leads, Body 5x5mm, Pitch 0.65mm"
  rrect33% 0.65x0.3 smd: 1(-2.075,1.95) 2(-2.075,1.3) 3(-2.075,0.65) 4(-2.075,0) 5(-2.075,-0.65) 6(-2.075,-1.3) 7(-2.075,-1.95) 8(2.075,-1.95) 9(2.075,-1.3) 10(2.075,-0.65) 11(2.075,0.65) 12(2.075,1.3) 13(2.075,1.95)
  silkscreen extent -2.5,-2.65 2.5,2.65, body extent -2.5,-2.5 2.5,2.5, height 0.91
PQ32 [mm] "Core"
  Keep-Out Layer board cut-out: -11,9 -11,16 11,16 11,9 10.045,9 10.062,9 5.517,12.321 0.013,13.5 -5.493,12.332 -10.045,9.02 -10.045,9.02 -10.045,9
  Keep-Out Layer board cut-out: -11,-16 -11,-9 -10.062,-9 -5.517,-12.321 -0.013,-13.5 5.493,-12.332 10.045,-9.02 10.045,-9.02 10.045,-9 11,-9 11,-16
  Keep-Out Layer board cut-out: 0,-6.725 -2.574,-6.213 -4.755,-4.755 -6.213,-2.574 -6.725,0 -6.725,0 -6.213,2.574 -4.755,4.755 -2.574,6.213 0,6.725 0,6.725 2.574,6.213 4.755,4.755 6.213,2.574 6.725,0 6.725,0 6.213,-2.574 4.755,-4.755 2.574,-6.213 0,-6.725
  silkscreen extent -11,-16 11,16, body extent -11.05,-15.97 11,16, height 0.25
SMB [mm] "Molded Diode, 2-Leads, Body 5.4x3.6mm, IPC Medium Density, based on OnSemi component dimensions"
  rect 2.159x2.743 smd: 1(-2.21,0) 2(2.21,0)
  silkscreen extent -3.94,-2.08 3.17,2.08, body extent -2.7,-1.8 2.7,1.8, height 2.32
VBE0015A-MFG [mm]
  round 0.265 smd paste+0 mask-1000: 1(-1.675,2.875) 11(1.675,2.875)
  rrect40% 0.7x0.25 smd paste+0 mask-1000: 2(-1.85,2.325) 3(-1.85,1.825) 4(-1.85,1.325) 5(-1.85,0.825) 8(1.85,1.325) 9(1.85,1.825) 10(1.85,2.325)
  rrect11% 1.9x3.95 smd paste-1000 mask-1000: 6(-1.3,-1.525) 7(1.3,-1.525)
  rrect40% 0.25x0.7 smd paste+0 mask-1000: 12(0.575,3.1) 13(0.075,3.1) 14(-0.425,3.1) 15(-0.925,3.1)
  Top Layer region: 2.15,2.7 2.169,2.704 2.185,2.715 2.196,2.731 2.2,2.75 2.2,2.75 2.2,2.9 2.193,2.925 2.175,2.943 2.15,2.95 2.15,2.95 1.85,2.95 1.812,2.958 1.779,2.979 1.758,3.012 1.75,3.05 1.75,3.05 1.75,3.4 1.746,3.419 1.735,3.435 1.719,3.446 1.7,3.45 1.7,3.45 1.55,3.45 1.531,3.446 1.515,3.435 1.504,3.419 1.5,3.4 1.5,3.4 1.5,2.75 1.504,2.731 1.515,2.715 1.531,2.704 1.55,2.7 1.55,2.7
  Top Layer region: -2.15,2.7 -2.169,2.704 -2.185,2.715 -2.196,2.731 -2.2,2.75 -2.2,2.75 -2.2,2.9 -2.193,2.925 -2.175,2.943 -2.15,2.95 -2.15,2.95 -1.85,2.95 -1.812,2.958 -1.779,2.979 -1.758,3.012 -1.75,3.05 -1.75,3.05 -1.75,3.4 -1.746,3.419 -1.735,3.435 -1.719,3.446 -1.7,3.45 -1.7,3.45 -1.55,3.45 -1.531,3.446 -1.515,3.435 -1.504,3.419 -1.5,3.4 -1.5,3.4 -1.5,2.75 -1.504,2.731 -1.515,2.715 -1.531,2.704 -1.55,2.7 -1.55,2.7
  silkscreen extent -2.92,-3.95 2.65,3.95, body extent -2.35,-3.6 2.35,3.55, height 0.25

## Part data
C1 C9 C32 C63 C74 C98: library part CMP-0083856-1, "CAP, CERM, 1 µF, 25 V,+/- 10%, X7R, 0603", Cap_Case=0603, Manufacturer=TDK, TempCo=X7R, Tolerance_%=10%, Value2=25V, ValueDisplayed=1µF
C2 C38 C39 C64: library part CMP-0006297-2, "CAP, CERM, 0.1 uF, 50 V, +/- 10%, X7R, 0402", Cap_Case=0402, Manufacturer=TDK, Supplier Part Number 1=445-5932-1-ND, TempCo=X7R, Tolerance_%=10%, Value1="0.039064 ohm", Value2=50V, ValueDisplayed=0.1uF
C3 C4 C5 C7 C8 C29 C30 C31 C36 C37 C65 C66 C67 C68 C69 C70 C71 C72 C73 C94 C95: library part CMP-0084048-1, "CAP, CERM, 0.022 µF, 1000 V,+/- 10%, X7R, AEC-Q200 Grade 1, 1206", Cap_Case=1206, Manufacturer=Kemet, TempCo=X7R, Tolerance_%=10%, Value2=1000V, ValueDisplayed=0.022µF
C6: library part CMP-0084048-1, "CAP, CERM, 0.022 µF, 1000 V,+/- 10%, X7R, AEC-Q200 Grade 1, 1206", Cap_Case=1206, Manufacturer=Kemet, TempCo=X7R, Tolerance_%=10%, Value2=1000V, ValueDisplayed=0.022uF
C10 C11 C75 C76: library part CMP-0006230-2, "CAP, CERM, 100 pF, 50 V, +/- 10%, X7R, 0402", Cap_Case=0402, Manufacturer="Wurth Elektronik", Supplier Part Number 1=732-7550-1-ND, TempCo=X7R, Tolerance_%=10%, Value1=Unknown, Value2=50V, ValueDisplayed=100pF
C12 C13 C14 C15 C16 C17 C18 C19 C20 C33 C34 C35 C46 C47 C48 C49 C50 C51 C52 C53 C54 C77 C78 C79 C80 C81 C82 C83 C84 C85: library part CMP-0008802-2, "CAP, CERM, 4.7 uF, 100 V, +/- 10%, X7R, 1206", Cap_Case=1206, Manufacturer=Samsung, TempCo=X7R, Tolerance_%=10%, Value1=Unknown, Value2=100V, ValueDisplayed=4.7uF
C21 C22 C55 C56 C86 C87: library part CMP-0006675-2, "CAP, CERM, 0.1 uF, 50 V, +/- 20%, X7R, 0402", Cap_Case=0402, Manufacturer=MuRata, Supplier Part Number 1=490-10701-1-ND, TempCo=X7R, Tolerance_%=20%, Value1=Unknown, Value2=50V, ValueDisplayed=0.1uF
C23 C24 C26 C27 C57 C58 C59 C60 C88 C89 C90 C91: library part CMP-0006305-2, "CAP, CERM, 100 pF, 50 V, +/- 10%, X7R, 0402", Cap_Case=0402, Manufacturer="Yageo America", Supplier Part Number 1=311-1419-1-ND, TempCo=X7R, Tolerance_%=10%, Value1=Unknown, Value2=50V, ValueDisplayed=100pF
C25 C28 C61 C62 C92 C93: library part CMP-0064946-2, "CAP, CERM, 0.1 uF, 50 V,+/- 10%, X7R, 0402", Cap_Case=0402, Manufacturer=TDK, Supplier Part Number 1=445-173610-1-ND, TempCo=X7R, Tolerance_%=10%, Value1=Unknown, Value2=50V, ValueDisplayed=0.1uF
D1 D3: library part CMP-0076998-2, "Diode, Schottky, 650 V, 1 A, SMB", Manufacturer="GeneSiC Semiconductor", Value1=1A, Value2=2V
FID1 FID2 FID3: library part CMP-0077181-1, "Fiducial mark.  There is nothing to buy or mount.", Manufacturer=N/A
L1 L2 L3 L4 L5 T1 T2 T3 T4 T5: library part CorePlace
R1 R17: library part CMP-0020812-2, "RES, 2.2, 5%, 0.125 W, 0805", Manufacturer="Yageo America", Power_W=125mW, Supplier Part Number 1=311-2.2ARCT-ND, TempCo="200 ppm/C", Tolerance_%=5%, Value2=0.125W, Value_Code=2R20, ValueDisplayed=2.2
R2 R4 R18 R20: library part CMP-0026284-2, "RES, 30.1 k, 1%, 0.063 W, AEC-Q200 Grade 0, 0402", Manufacturer=Vishay-Dale, Power_W=63mW, Supplier Part Number 1=541-30.1KLCT-ND, TempCo="100 ppm/C", Tolerance_%=1%, Value2=0.063W, Value_Code=30k1, ValueDisplayed=30.1k
R3 R19: library part CMP-0026825-5, "RES, 10 k, 5%, 0.063 W, AEC-Q200 Grade 0, 0402", Manufacturer=Vishay-Dale, Power_W=63mW, Supplier Part Number 1=541-10KJCT-ND, TempCo="200 ppm/C", Tolerance_%=5%, Value2=0.063W, Value_Code=10k0, ValueDisplayed=10k
R5 R6 R7 R8 R13 R14 R15 R16 R21 R22 R23 R24: library part CMP-0027006-2, "RES, 51, 5%, 0.0625 W, 0402", Manufacturer="Yageo America", Power_W=62.5mW, Supplier Part Number 1=311-51JRCT-ND, TempCo="100 ppm/C", Tolerance_%=5%, Value2=0.0625W, Value_Code=51R0, ValueDisplayed=51
R10 R11 R12 R25: library part CMP-0027004-2, "RES, 0, 5%, 0.063 W, 0402", Manufacturer="Yageo America", Power_W=63mW, Supplier Part Number 1=311-0.0JRCT-ND, TempCo="200 ppm/C", Tolerance_%=5%, Value2=0.063W, Value_Code=0000, ValueDisplayed=0
U1: library part CMP-0120607-2, Manufacturer="Texas Instruments", Operating Temperature Range=to, PartNumber=LMG3650
U2 U16: library part CMP-0013548-2, "4A/6A Isolated Dual-Channel Gate Driver, NPL0013A (VLGA-13)", Alternate Manufacturer="Texas Instruments"
U3: library part CMP-0120607-2, Manufacturer="Texas Instruments", Operating Temperature Range=to, PartNumber=LMG3656
U4 U5 U6 U7 U11 U12 U13 U14 U18 U19 U20 U21: library part CMP-0043784-1, "100-V, 64-A GaN with Integrated Driver", Manufacturer="Texas Instruments", Max Supply Voltage=5.25V, Min Supply Voltage=4.75V, Nominal Supply Current=3mA, Operating Temperature Range="-40°C to +125°C"
U15: library part CMP-0120607-2, Manufacturer="Texas Instruments", Operating Temperature Range=to
U17: library part CMP-0122864-1, "650V 25mΩ GaN FET With Integrated Driver and Protection", Manufacturer="Texas Instruments", Max Supply Voltage=26V, Min Supply Voltage=9V, Nominal Supply Current=0.7-5mA, Operating Temperature Range="-40°C to +175°C"

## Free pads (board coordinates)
  rrect50% 3x3 / inner rrect50% 2.5x3 / far side rrect50% 3x3 hole 1.5: 8(22.659,113.579) 8(22.659,115.34) 8(22.659,133.121) 8(22.659,134.881) 8(22.666,43.25) 8(22.666,45.01) 8(22.666,63.24) 8(22.666,65)
  rrect50% 2x5 smd far side: 8(22.665,32.008) 8(22.842,12.447)
  rrect50% 2x5 smd: 8(22.698,170.047) 8(22.875,150.486)
  rrect50% 3x2.5 / inner rrect50% 2x2.5 / far side rrect50% 3x2.5 hole 1.3: 8(64.486,113.214) 8(64.486,127.199) 8(64.5,114.765) 8(64.5,128.75)
  rrect50% 3x4 smd: 8(64.5,163.935) 8(64.507,149.937)
  rrect50% 4x5.5 smd far side: 8(64.553,24.744) 8(64.691,45.221) 8(64.744,56.713)
  rrect50% 4x5.5 smd: 8(64.553,56.744) 8(64.691,45.221)
  rrect50% 3x5.5 smd far side: 8(64.691,13.221)
  rect 4x3.2 / inner rrect50% 2x3.5 / far side rect 4x3.2 hole 1.5: 8(65.5,46.364) 8(65.5,44.125) 8(65.553,57.856) 8(65.553,55.617)
  rrect50% 0.8x2 smd: P1(6.216,1) P1(6.216,138.962) P3(7.716,1) P3(7.716,138.962) P5(9.216,1) P5(9.216,138.962) S1(74.015,1) S1(74.015,69) S1(74.015,139) S3(72.515,1) S3(72.515,69) S3(72.515,139) S5(71.015,1) S5(71.015,69) S5(71.015,139)
  rrect50% 0.8x2 smd far side: P2(6.216,1) P2(6.216,138.962) P4(7.716,1) P4(7.716,138.962) P6(9.216,1) P6(9.216,138.962) S2(74.015,1) S2(74.015,69) S2(74.015,139) S4(72.515,1) S4(72.515,69) S4(72.515,139) S6(71.015,1) S6(71.015,69) S6(71.015,139)
  rect 2.5x2 hole 0.762: P7(15.463,138.962) P7(15.482,1) P8(23.48,1) P8(23.48,138.962) P9(31.21,1) P9(31.21,138.962) S7(68.74,1) S7(68.74,69) S7(68.74,139) S8(65.5,1) S8(65.5,69) S8(65.5,139)

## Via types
v1: diameter 0.6, hole 0.3, Top Layer to Bottom Layer 1, tented both sides, 748 vias
v2: diameter 0.6, hole 0.3, Layer 2 to Layer 3, tented both sides, 41 vias
v3: diameter 0.6, hole 0.3, Layer 6 to Layer 7, tented both sides, 38 vias
v4: diameter 0.6, hole 0.3, Layer 8 to Layer 9, tented both sides, 35 vias
v5: diameter 0.6, hole 0.3, Layer 4 to Layer 5, tented both sides, 31 vias
v6: diameter 0.6, hole 0.3, Layer 2 to Layer 9, tented both sides, 24 vias
v7: diameter 0.6, hole 0.3, Layer 2 to Layer 5, tented both sides, 22 vias
v8: diameter 0.7, hole 0.4, Top Layer to Bottom Layer 1, tented both sides, 18 vias
v9: diameter 0.6, hole 0.3, Layer 6 to Layer 9, tented both sides, 15 vias

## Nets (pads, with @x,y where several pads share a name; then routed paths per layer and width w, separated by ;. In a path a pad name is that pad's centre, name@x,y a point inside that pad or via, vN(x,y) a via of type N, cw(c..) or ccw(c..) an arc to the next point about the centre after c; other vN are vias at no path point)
5V-s_2: C21.1 C22.1 pad.S5@71.015,1 U6.3 U7.3 | length 6.3
  Top Layer w0.254: v8(70.535,2.775) 71.015,2.295 pad.S5@71.015,1 ; C21.1@71.684,16.522 71.798,16.407 71.798,15.969 v1(71.864,15.903) 71.864,15.809 72.225,15.449 U6.3@72.225,14.675 ; C22.1@71.7,31.834 71.7,31.734 72.049,31.384 U7.3@72.049,29.725
  other v1: 71.917,30.886
5V-s_4: C55.1 C56.1 pad.S5@71.015,69 U13.3 U14.3 | length 6.3
  Top Layer w0.254: v8(70.535,70.775) 71.015,70.295 pad.S5@71.015,69 ; C56.1@71.66,84.542 71.66,83.795 v1(71.668,83.788) 72.016,83.44 U14.3@72.016,82.637 ; v1(71.759,99.141) 71.759,99.048 72.049,98.757 U13.3@72.049,97.725
  Top Layer w0.5: C55.1@71.547,99.791 71.597,99.741 71.597,99.33 71.759,99.168 v1(71.759,99.141)
5V-s_5: C86.1 C87.1 pad.S5@71.015,139 U20.3 U21.3 | length 5.6
  Top Layer w0.254: v8(70.535,140.775) 71.015,140.295 pad.S5@71.015,139 ; C87.1@72.197,169.184 72.126,169.184 v1(72.111,169.169) 72.111,168.433 72.5,168.044 U20.3@72.5,167.192 ; C86.1@72.282,154.44 v1(72.282,153.893) 72.282,153.052 U21.3@72.284,153.05
12Vp_2: C2.1 C9.1 pad.P2@6.216,1 R1.1 R12.1 U2.4 U2.7 U2.10 | length 38.1
  Top Layer w0.254: U2.4@7.989,7.93 8.001,7.918 8.001,7.347 8.151,7.198 v1@8.151,6.972 ; v1@8.217,6.945 8.347,6.814 8.347,6.663 C9.1@8.695,6.315 ; U2.10@8.639,12.08 8.662,12.103 8.662,12.467 9.034,12.838 v1(9.034,12.932) ; U2.7@9.939,7.93 9.942,7.933 9.942,8.549 v1(9.944,8.552)
  Top Layer w0.5: v1(6.25,25.595) R1.1@7.063,26.181
  Layer 3 w0.254: v1(6.903,2.825) v1@6.903,2.906 ; v1(9.034,12.932) 7.372,11.271 7.372,8.191 8.151,7.412 8.151,7.104 v1(8.217,7.038) 9.665,8.486 9.878,8.486 v1(9.944,8.552)
  Layer 4 w0.254: v1(8.217,7.038) 8.217,6.558 10.483,4.292
  Layer 2 w0.254: v1(6.25,25.595) 5.651,24.997 5.651,17.249 9.034,13.867 v1(9.034,12.932)
  Bottom Layer 1 w0.254: pad.P2@6.216,1 6.303,1.088 6.303,2.226 v1(6.903,2.825) 6.969,2.891 7.386,2.891 9.063,4.568 R12.1@9.163,4.568 ; C2.1@8.72,11.929 8.893,12.102 C2.1@8.961,12.102 9.034,12.174 v1(9.034,12.932)
12Vp_5: C64.1 C74.1 pad.P2@6.216,138.962 R17.1 R25.1 U16.4 U16.7 U16.13 | length 34
  Top Layer w0.254: v1(6.903,140.787) 6.996,140.787 7.184,140.974 7.772,140.974 8.84,142.043 9.327,142.043 9.637,142.353 9.81,142.526 R25.1@9.91,142.526
  Layer 3 w0.254: v1(6.903,140.787) v1@6.903,140.867
  Layer 9 w0.254: v1(5.663,164.769) 5.597,164.703 5.597,164.508 5.537,164.447 5.537,156.078 8.317,153.299 8.317,150.099 5.905,147.688 v1(5.905,146.144)
  Bottom Layer 1 w0.254: U16.7@5.882,145.372 5.905,145.395 v1(5.905,146.144) ; pad.P2@6.216,138.962 6.303,139.049 6.303,140.187 v1(6.903,140.787) ; C74.1@7.357,144.047 7.832,144.522 U16.4@7.832,145.372 7.855,145.395 7.855,146.024 8.115,146.284 v1(8.115,146.378) ; v1(9.782,148.226) U16.13@9.782,149.522 9.782,150.692 9.955,150.865 C64.1@10.04,150.865
  Bottom Layer 1 w0.5: v1(5.663,164.769) 5.682,164.75 5.843,164.75 6.344,164.249 R17.1@6.344,164.084
54Vout_2: C12.1 C13.1 C14.1 C15.1 C16.1 C17.1 C18.1 C19.1 C20.1 C33.1 pad.S8@65.5,1 U4.7 U4.8 U5.7 U5.8 | length 1.4
  Top Layer w0.254: v1(70.203,19.733) 70.303,19.633 U4.8@71.528,19.633
  other v1: 64.768,0.321 65.509,0.321 66.191,0.321 64.768,0.984 66.191,1.016 64.768,1.691 65.491,1.691 66.191,1.691 64.768,2.366 65.491,2.366 66.191,2.366 65.285,4.405 66.585,4.405 67.885,4.405 65.285,5.545 66.585,5.545 67.885,5.545 66.191,19.733 67.603,19.733 68.903,19.733 66.191,20.8 67.603,20.873 68.903,20.873 70.203,20.873 63.988,32.048 64.972,32.048 65.955,32.048 66.938,32.048 67.922,32.048 68.905,32.048 69.889,32.048 66.041,33 67.045,33 68.11,33
54Vout_4: C34.1 C46.1 C47.1 C48.1 C49.1 C50.1 C51.1 C52.1 C53.1 C54.1 pad.S8@65.5,69 U11.7 U11.8 U12.7 U12.8 | length 1.4
  Top Layer w0.254: v1(70.224,87.733) 70.324,87.633 U11.8@71.549,87.633
  other v1: 64.768,68.321 65.509,68.321 66.191,68.321 64.768,68.984 66.191,69.016 64.768,69.691 65.491,69.691 66.191,69.691 64.768,70.366 65.491,70.366 66.191,70.366 65.285,72.205 66.585,72.205 67.885,72.205 65.285,73.345 66.585,73.345 67.885,73.345 66.262,87.717 67.624,87.733 68.924,87.733 66.262,88.873 67.624,88.873 68.924,88.873 70.224,88.873 63.988,100.048 64.972,100.048 65.955,100.048 66.938,100.048 67.922,100.048 68.905,100.048 69.889,100.048 66.041,101 67.045,101 68.11,101
54Vout_5: C35.1 C77.1 C78.1 C79.1 C80.1 C81.1 C82.1 C83.1 C84.1 C85.1 pad.S8@65.5,139 U18.7 U18.8 U19.7 U19.8 | length 2.7
  Top Layer w0.254: v1(67.709,142.604) 67.809,142.504 U19.8@69.034,142.504 ; v1(70.675,157.538) 70.775,157.438 U18.8@72,157.438
  other v1: 64.768,138.321 65.509,138.321 66.191,138.321 64.768,138.984 66.191,139.016 64.768,139.691 65.491,139.691 66.191,139.691 64.768,140.366 65.491,140.366 66.191,140.366 65.109,142.604 66.409,142.604 65.109,143.744 66.409,143.744 67.709,143.744 68.075,157.538 69.375,157.538 68.075,158.678 69.375,158.678 70.675,158.678 63.988,170.048 64.972,170.048 65.955,170.048 66.938,170.048 67.922,170.048 68.905,170.048 69.889,170.048 66.041,171 67.045,171 68.11,171
AGND_2: C21.2 C22.2 C23.2 C24.2 C26.2 C27.2 pad.S6@71.015,1 U6.4 U7.4 | length 20.6
  Top Layer w0.254: C22.2@71.562,32.631 C27.2@72.804,32.631 C26.2@74.023,32.631 C26.2@74.026,32.633 ; C22.2@71.656,32.824 71.531,32.7 71.531,32.6 71.483,32.551 71.42,32.551 70.852,31.983 70.852,31.065 71.549,30.367 71.549,28.727 v1(72.155,28.121) ; U6.4@71.725,14.675 71.723,14.677 71.723,15.118 71.057,15.784 71.057,17.095 71.411,17.449 71.511,17.449 71.684,17.622 C21.2@71.684,17.722 71.684,17.707 C21.2@71.857,17.534 ; U6.4@71.727,14.452 71.727,14.201 v1(72.238,13.69) ; v1(72.234,18.372) 71.857,17.995 C21.2@71.857,17.534 ; C23.2@73.85,17.534 C24.2@72.725,17.534 C21.2@71.857,17.534
  Bottom Layer 1 w0.254: pad.S6@71.015,1 71.065,1.051 71.065,2.285 71.313,2.532 71.313,3.41 v1(71.407,3.505) 71.407,4.441 v8(72.165,5.198)
  other v1: 71.104,30.646
AGND_4: C55.2 C56.2 C57.2 C58.2 C59.2 C60.2 pad.S6@71.015,69 U13.4 U14.4 | length 21
  Top Layer w0.254: C56.2@71.493,85.49 71.48,85.477 71.218,85.477 71.026,85.284 71.026,83.543 71.547,83.021 71.547,82.637 71.547,81.833 71.618,81.763 v1(71.618,81.669) ; v1(72.165,96.409) 71.551,97.022 71.551,97.723 U13.4@71.549,97.725 71.547,97.727 71.547,98.184 v1(70.928,98.803) 70.92,98.811 70.92,100.455 71.217,100.752 71.227,100.742 C57.2@73.874,100.742 ; C60.2@72.887,85.332 C59.2@74.032,85.332 C59.2@74.112,85.332
  Top Layer w0.6: C56.2@71.653,85.75 71.653,85.85 71.908,85.85 72.26,86.201 v1(72.26,86.214) 71.71,85.665 72.536,85.665 72.769,85.432 72.887,85.432 C60.2@72.887,85.332
  Bottom Layer 1 w0.254: pad.S6@71.015,69 71.065,69.051 71.065,70.285 71.313,70.532 71.313,71.41 71.473,71.571 71.473,71.836 72.165,72.527 v8(72.165,73.198)
  other v1: 71.407,71.505
AGND_5: C86.2 C87.2 C88.2 C89.2 C90.2 C91.2 pad.S6@71.015,139 U20.4 U21.4 | length 19.9
  Top Layer w0.254: v1(71.407,141.505) 72.165,142.262 v8(72.165,143.198) ; C86.2@72.031,155.439 72.204,155.612 C86.2@72.204,155.712 71.654,155.712 71.301,155.359 71.301,153.941 71.784,153.458 U21.4@71.784,153.05 71.784,152.435 v1(72.119,152.101) ; v1(72.501,165.767) 72,166.268 U20.4@72,167.192 72,167.653 v1(71.438,168.215) 71.438,168.299 71.195,168.542 71.195,170.016 71.548,170.369 C87.2@72.111,170.369 72.111,170.269 72.284,170.096 72.384,170.096 72.437,170.042 C89.2@73.209,170.042 C88.2@74.242,170.042
  Top Layer w0.6: C86.2@72.204,155.712 C91.2@73.241,155.712 C90.2@74.242,155.712
  Bottom Layer 1 w0.254: pad.S6@71.015,139 71.085,139.07 71.085,140.232 71.313,140.46 71.313,141.41 v1(71.407,141.505)
  other v1: 72.708,156.132
B+_2: C7.1 C8.1 C29.1 C30.1 C31.1 C36.1 C37.1 pad.P8@23.48,1 U1.9
  other v1: 22.71,0.379 23.45,0.379 24.133,0.379 22.749,0.984 24.172,1.016 22.749,1.691 23.472,1.691 24.172,1.691 22.767,2.387 23.508,2.387 24.19,2.387 7.237,30.246 9.642,30.253 12.048,30.259 14.453,30.266 16.858,30.272 19.264,30.322 7.237,30.969 9.642,30.976 12.048,30.982 14.453,30.989 16.858,30.995 19.264,31.002
B+_5: C69.1 C70.1 C71.1 C72.1 C73.1 C94.1 C95.1 pad.P8@23.48,138.962 U15.9
  other v1: 22.749,138.945 24.172,138.978 22.749,139.653 23.472,139.653 24.172,139.653 22.749,140.348 23.489,140.348 24.172,140.348 6.915,167.987 9.321,167.994 11.726,168.001 14.132,168.007 16.537,168.014 18.942,168.063 6.915,168.711 9.321,168.717 11.726,168.724 14.132,168.73 16.537,168.737 18.943,168.743
B-_2: C2.2 C7.2 C8.2 C9.2 C10.2 C11.2 C29.2 C30.2 C31.2 C36.2 C37.2 C38.1 pad.P3@7.716,1 pad.P4@7.716,1 pad.P7@15.482,1 R3.1 R4.1 U2.1 U2.5 U2.8 U3.1 U3.2 U3.3 U3.4 | length 29.2
  Top Layer w0.254: U2.1@6.016,7.93 6.016,7.732 5.696,7.411 5.696,5.606 5.844,5.458 6.15,5.458 6.323,5.285 6.323,5.218 C10.2@6.323,5.205 ; U2.1@6.039,7.93 U2.1@6.056,7.947 ; C11.2@7.421,5.205 C11.2@7.434,5.218 ; v1@8.182,5.088 C9.2@8.347,5.088 ; v1@8.217,5.218 C9.2@8.347,5.088 ; C9.2@8.347,4.297 8.347,4.596 C9.2@8.464,4.712 ; v1@8.381,8.755 8.639,8.497 U2.5@8.639,7.93 ; U2.8@9.939,11.905 U2.8@9.962,11.882 ; U2.8@9.939,12.08 9.939,12.619 10.161,12.841 v1(10.161,12.935) ; R3.1@9.98,5.218 9.98,5.118 9.576,4.715 C9.2@8.695,4.715 8.695,4.74 C9.2@8.347,5.088
  Top Layer w0.5: C10.2@6.323,5.218 C11.2@7.421,5.218 ; C11.2@7.421,5.205 v1(7.971,5.205) ; pad.P3@7.716,1 v1(7.716,2.333) 7.716,3.665 C9.2@8.347,4.297
  Layer 2 w0.254: v1(7.971,5.205) 8.844,6.078 8.844,7.298 8.217,7.925 8.217,10.99 v1(10.161,12.935)
  Bottom Layer 1 w0.254: v1@7.971,5.111 v1(7.971,5.205) 8.521,5.205 8.861,5.545 8.861,5.645 9.034,5.818 9.134,5.818 ; C2.2@10.161,12.102 v1(10.161,12.935) ; 10.334,5.818 11.289,5.818 11.863,6.393 v1@11.863,7.582 ; v1@16.644,7.564 v1@16.663,7.582
  Bottom Layer 1 w0.5: pad.P4@7.716,1 v1(7.716,2.333)
  other v1: 14.712,0.379 15.474,0.379 16.173,0.379 14.712,0.984 16.173,1.016 14.712,1.691 15.474,1.691 16.173,1.691 14.75,2.387 15.491,2.387 16.173,2.387 11.863,7.382 13.063,7.382 14.263,7.382 15.463,7.382 16.663,7.382 17.863,7.382 19.063,7.382 20.263,7.382 11.863,8.67 13.063,8.67 14.263,8.67 15.463,8.67 16.663,8.67 17.863,8.67 19.063,8.67 20.263,8.67 8.217,8.755 11.863,9.89 13.063,9.89 14.263,9.89 15.463,9.89 16.663,9.89 17.863,9.89 19.063,9.89 20.263,9.89 11.863,11.11 13.063,11.11 14.263,11.11 15.463,11.11 16.663,11.11 17.863,11.11 19.063,11.11 20.263,11.11 11.863,12.4 13.063,12.4 14.263,12.4 15.463,12.4 16.663,12.4 17.863,12.4 19.063,12.4 20.263,12.4 6.023,33.799 7.226,33.802 8.429,33.806 9.631,33.809 10.834,33.812 12.037,33.815 13.24,33.819 14.442,33.822 15.645,33.825 16.848,33.828 18.05,33.832 19.253,33.835
B-_5: C39.2 C64.2 C69.2 C70.2 C71.2 C72.2 C73.2 C74.2 C75.2 C76.2 C94.2 C95.2 pad.P3@7.716,138.962 pad.P4@7.716,138.962 pad.P7@15.463,138.962 R19.1 R20.1 U16.1 U16.5 U16.11 U17.1 U17.2 U17.3 U17.4 | length 9.2
  Top Layer w0.254: pad.P3@7.716,138.962 v1(7.716,140.294)
  Bottom Layer 1 w0.254: U16.5@7.182,145.372 v1(7.182,146.082) ; 7.705,141.257 7.716,141.246 ; v1(8.482,148.226) U16.11@8.482,149.522 8.503,149.543 8.503,149.978 8.84,150.315 C64.2@8.84,150.865 ; C76.2@8.733,142.476 C75.2@9.91,142.476 ; v1(9.671,146.196) 9.671,146.102 9.782,145.991 U16.1@9.782,145.372
  Bottom Layer 1 w0.5: pad.P4@7.716,138.962 v1(7.716,140.294) 7.716,141.246
  other v1: 14.731,138.945 16.154,138.978 14.731,139.653 15.455,139.653 16.154,139.653 14.731,140.348 15.472,140.348 16.154,140.348 8.082,142.476 11.75,145.253 12.95,145.253 14.15,145.253 15.35,145.253 16.55,145.253 17.75,145.253 18.95,145.253 20.15,145.253 11.75,146.341 12.95,146.341 14.15,146.341 15.35,146.341 16.55,146.341 17.75,146.341 18.95,146.341 20.15,146.341 11.75,147.561 12.95,147.561 14.15,147.561 15.35,147.561 16.55,147.561 17.75,147.561 18.95,147.561 20.15,147.561 11.75,148.781 12.95,148.781 14.15,148.781 15.35,148.781 16.55,148.781 17.75,148.781 18.95,148.781 20.15,148.781 11.75,149.861 12.95,149.861 14.15,149.861 15.35,149.861 16.55,149.861 17.75,149.861 18.95,149.861 20.15,149.861 6.062,171.565 7.265,171.568 8.468,171.572 9.671,171.575 10.873,171.578 12.076,171.581 13.279,171.585 14.482,171.588 15.684,171.591 16.887,171.594 18.09,171.598 19.292,171.601
Drv-AH_2: U4.2 U7.10 | length 2.8
  Top Layer w0.254: U4.2@72.528,23.333 72.528,24.094 72.716,24.282 72.716,25.153 72.549,25.32 U7.10@72.549,26.025
Drv-AH_4: U11.2 U13.10 | length 2.8
  Top Layer w0.254: U11.2@72.549,91.333 72.549,92.155 72.734,92.34 72.734,93.211 72.549,93.395 U13.10@72.549,94.025
Drv-AH_5: U18.2 U20.10 | length 2.5
  Top Layer w0.254: U18.2@73,161.138 73.002,161.14 73.002,161.733 73.176,161.908 73.176,162.778 73.002,162.953 73.002,163.49 U20.10@73,163.492
Drv-BH_2: U5.2 U6.10 | length 4.9
  Top Layer w0.254: U5.2@70.21,8.005 70.212,8.007 70.212,8.415 70.482,8.685 71.949,8.685 72.725,9.46 U6.10@72.725,10.975
Drv-BH_4: U12.2 U14.10 | length 4.8
  Top Layer w0.254: U12.2@70.212,76.028 70.212,76.456 70.361,76.605 71.883,76.605 72.516,77.237 U14.10@72.516,78.937
Drv-BH_5: U19.2 U21.10 | length 5.4
  Top Layer w0.254: U19.2@70.034,146.204 70.034,146.928 70.183,147.077 72.142,147.077 72.784,147.718 U21.10@72.784,149.35
FLT_2: R4.2 U3.5 | length 1.3
  Top Layer w0.254: U3.5@16.663,5.251 v1(16.665,5.25) U3.5@16.667,5.248
  Bottom Layer 1 w0.254: v1(16.665,5.25) 17.145,5.729 17.145,6.153 R4.2@17.254,6.262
